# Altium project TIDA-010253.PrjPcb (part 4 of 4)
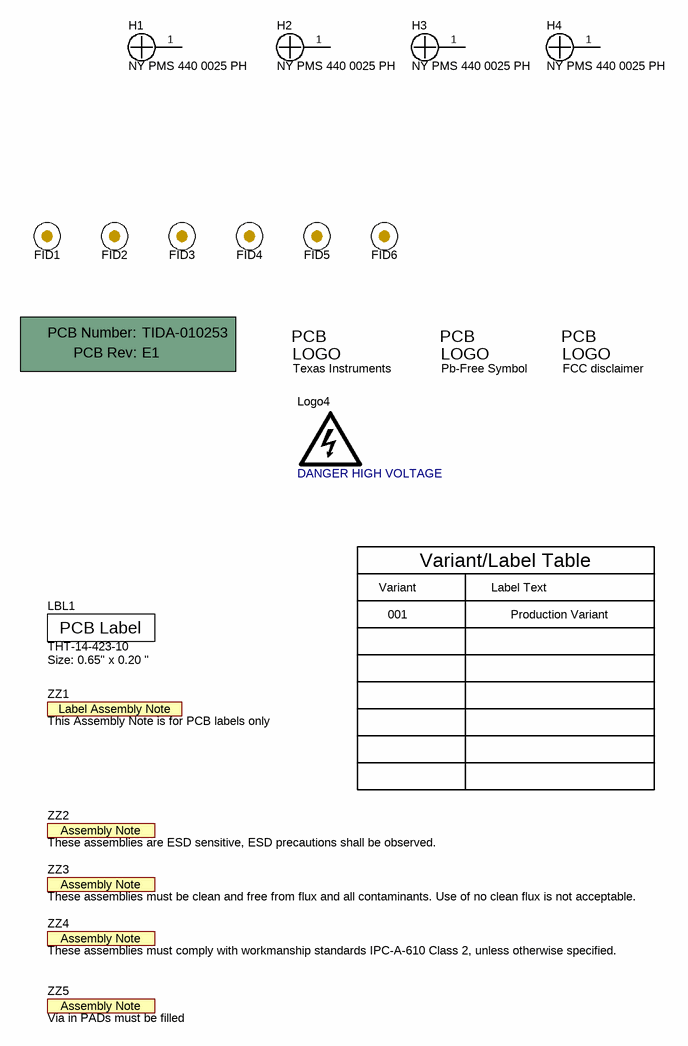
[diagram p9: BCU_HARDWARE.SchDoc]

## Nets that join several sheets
BQ_12V: DaisyChain (R38.2 R55.2), PowerSupply (C103.1 R137.2 R146.1 U23.1)
GND: DaisyChain (38 pins), PowerSupply (F2.2 L3.2 L7.2), MCU_DockHearder_V3 (77 pins), Driver and output (7 pins), BCU Board_CAN485 (36 pins)
PGND: PowerSupply (61 pins), Driver and output (59 pins)
VCC3V3: PowerSupply (6 pins), MCU_DockHearder_V3 (13 pins), BCU Board_CAN485 (8 pins)
VCC5V: PowerSupply (12 pins), MCU_DockHearder_V3 (6 pins), Driver and output (5 pins), BCU Board_CAN485 (9 pins)
VDDIO: DaisyChain (15 pins), PowerSupply (R129.1 R130.1 R131.1), MCU_DockHearder_V3 (12 pins), Driver and output (13 pins)
AM263X_CAN2_RX: MCU_DockHearder_V3 (J29.94), BCU Board_CAN485 (R25.1)
AM263X_CAN2_TX: MCU_DockHearder_V3 (J29.95), BCU Board_CAN485 (R23.1)
BQ0_FAULT: DaisyChain (R42.1 R53.1 U10.2), MCU_DockHearder_V3 (J29.60)
BQ0_INH: DaisyChain (R44.2 U10.16), PowerSupply (D32.2)
BQ0_INH_L: DaisyChain (C29.1 D9.1 R44.1), MCU_DockHearder_V3 (J29.58)
BQ0_SPI_CS: DaisyChain (R49.2 U10.7), MCU_DockHearder_V3 (R167.2)
BQ0_SPI_MISO: DaisyChain (R48.2 U10.5), MCU_DockHearder_V3 (R164.2)
BQ0_SPI_MOSI: DaisyChain (R47.2 U10.4), MCU_DockHearder_V3 (R163.2)
BQ0_SPI_SCK: DaisyChain (R46.2 U10.6), MCU_DockHearder_V3 (R165.2)
BQ0_SPIRDY: DaisyChain (R41.1 U10.8), MCU_DockHearder_V3 (J29.55)
BQ1_FAULT: DaisyChain (R59.1 R70.1 U11.2), MCU_DockHearder_V3 (J29.51)
BQ1_INH: DaisyChain (R61.2 U11.16), PowerSupply (D33.2)
BQ1_INH_L: DaisyChain (C40.1 D14.1 R61.1), MCU_DockHearder_V3 (J29.53)
BQ1_SPI_CS: DaisyChain (R66.2 U11.7), MCU_DockHearder_V3 (R172.2)
BQ1_SPI_MISO: DaisyChain (R65.2 U11.5), MCU_DockHearder_V3 (R169.2)
BQ1_SPI_MOSI: DaisyChain (R64.2 U11.4), MCU_DockHearder_V3 (R168.2)
BQ1_SPI_SCK: DaisyChain (R63.2 U11.6), MCU_DockHearder_V3 (R170.2)
BQ1_SPIRDY: DaisyChain (R58.1 U11.8), MCU_DockHearder_V3 (J29.49)
CAN0_RX: MCU_DockHearder_V3 (J29.80), BCU Board_CAN485 (R12.1)
CAN0_TX: MCU_DockHearder_V3 (J29.82), BCU Board_CAN485 (R10.1)
CONT_SPI_CS: MCU_DockHearder_V3 (R182.2), Driver and output (R114.1 R115.1)
CONT_SPI_MISO: MCU_DockHearder_V3 (R179.2), Driver and output (R107.1 R109.1)
CONT_SPI_MOSI: MCU_DockHearder_V3 (R178.2), Driver and output (R110.1 R112.1)
CONT_SPI_SCK: MCU_DockHearder_V3 (R180.2), Driver and output (R104.1 R105.1)
DRV_FAULT_ALL_L: MCU_DockHearder_V3 (J29.127 J45.3), Driver and output (R121.2)
HS_CS: MCU_DockHearder_V3 (J17.12 R198.2), Driver and output (R80.1)
HS_DIAG: MCU_DockHearder_V3 (J29.54), Driver and output (U13.14)
HS_EN1: MCU_DockHearder_V3 (J29.90), Driver and output (U13.3)
HS_EN2: MCU_DockHearder_V3 (J29.92), Driver and output (U13.4)
HS_EN3: MCU_DockHearder_V3 (J29.106), Driver and output (U13.5)
HS_EN4: MCU_DockHearder_V3 (J29.104), Driver and output (U13.6)
HSD_FAULT1: MCU_DockHearder_V3 (J29.123 J45.1), Driver and output (5 pins)
HSD_SEH: MCU_DockHearder_V3 (J29.50), Driver and output (R76.1 R230.2)
HSD_SEL: MCU_DockHearder_V3 (J29.52), Driver and output (R77.1 R231.2)
IPROPI1: MCU_DockHearder_V3 (J17.4 R184.2), Driver and output (C69.1 R99.2 R111.2)
IPROPI2: MCU_DockHearder_V3 (J17.6 R188.2), Driver and output (C66.1 R91.2 R93.2)
IPROPI3: MCU_DockHearder_V3 (J17.8 R192.2), Driver and output (C70.1 R101.2 R113.2)
IPROPI4: MCU_DockHearder_V3 (J17.10 R194.2), Driver and output (C67.1 R92.2 R94.2)
KL15_OK_G: PowerSupply (D30.1 Q9.1 R128.1), MCU_DockHearder_V3 (J29.62)
LS_EN1: MCU_DockHearder_V3 (J29.88), Driver and output (R96.1)
LS_EN2: MCU_DockHearder_V3 (J29.86), Driver and output (R102.1)
LS_EN3: MCU_DockHearder_V3 (J29.96), Driver and output (R97.1)
LS_EN4: MCU_DockHearder_V3 (J29.100), Driver and output (Q6.3 R103.1)
LS_EN_COM: MCU_DockHearder_V3 (J29.102), Driver and output (16 pins)
LS_OUT_COM_S: MCU_DockHearder_V3 (J17.14 R229.2), Driver and output (C68.1 R90.1 R95.2)
LSD_FAULT1: MCU_DockHearder_V3 (J29.125 J45.4), Driver and output (5 pins)
LSD_FAULT2: MCU_DockHearder_V3 (J29.121 J45.2), Driver and output (5 pins)
MCU_WAKE: PowerSupply (R147.1), MCU_DockHearder_V3 (J29.64)
PCHG_IO0: MCU_DockHearder_V3 (J29.108), Driver and output (J14.3)
RS485_D: MCU_DockHearder_V3 (J29.78), BCU Board_CAN485 (R215.1)
RS485_DE: MCU_DockHearder_V3 (J29.74), BCU Board_CAN485 (R214.1)
RS485_R: MCU_DockHearder_V3 (J29.76), BCU Board_CAN485 (R209.1)
RS485_RE: MCU_DockHearder_V3 (J29.72), BCU Board_CAN485 (R211.1)
UIR_nFAULT: MCU_DockHearder_V3 (J29.110), Driver and output (J25.7)
UIR_SN65_EN: MCU_DockHearder_V3 (J29.101), Driver and output (J25.18)
UIR_SPI_CLK: MCU_DockHearder_V3 (R176.2), Driver and output (J25.17)
UIR_SPI_CS: MCU_DockHearder_V3 (R177.2), Driver and output (J25.15)
UIR_SPI_MISO: MCU_DockHearder_V3 (R175.2), Driver and output (J25.13)
UIR_SPI_MOSI: MCU_DockHearder_V3 (R174.2), Driver and output (J25.11)

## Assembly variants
Variant of TIDA-010253: not fitted C60 C61 C62 C63 C64 C65 C66 C67 C69 C70 R91 R92 R93 R94 R96 R97 R98 R99 R100 R101 R102 R103 R104 R105 R106 R107 R108 R109 R110 R111 R112 R113 R114 R115 R116 R159 U17 U18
